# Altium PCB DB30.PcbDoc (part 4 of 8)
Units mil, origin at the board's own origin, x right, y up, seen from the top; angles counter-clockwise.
Board outline 3236.22 x 4456.69 mil, 8 copper layers (Top Layer, MidLayer1, MidLayer2, GND-Layer5, MidLayer3, VCC, MidLayer4, Bottom Layer), stack 61.8 mil thick; 219 components, 472 nets, 1811 pads, 1561 vias.
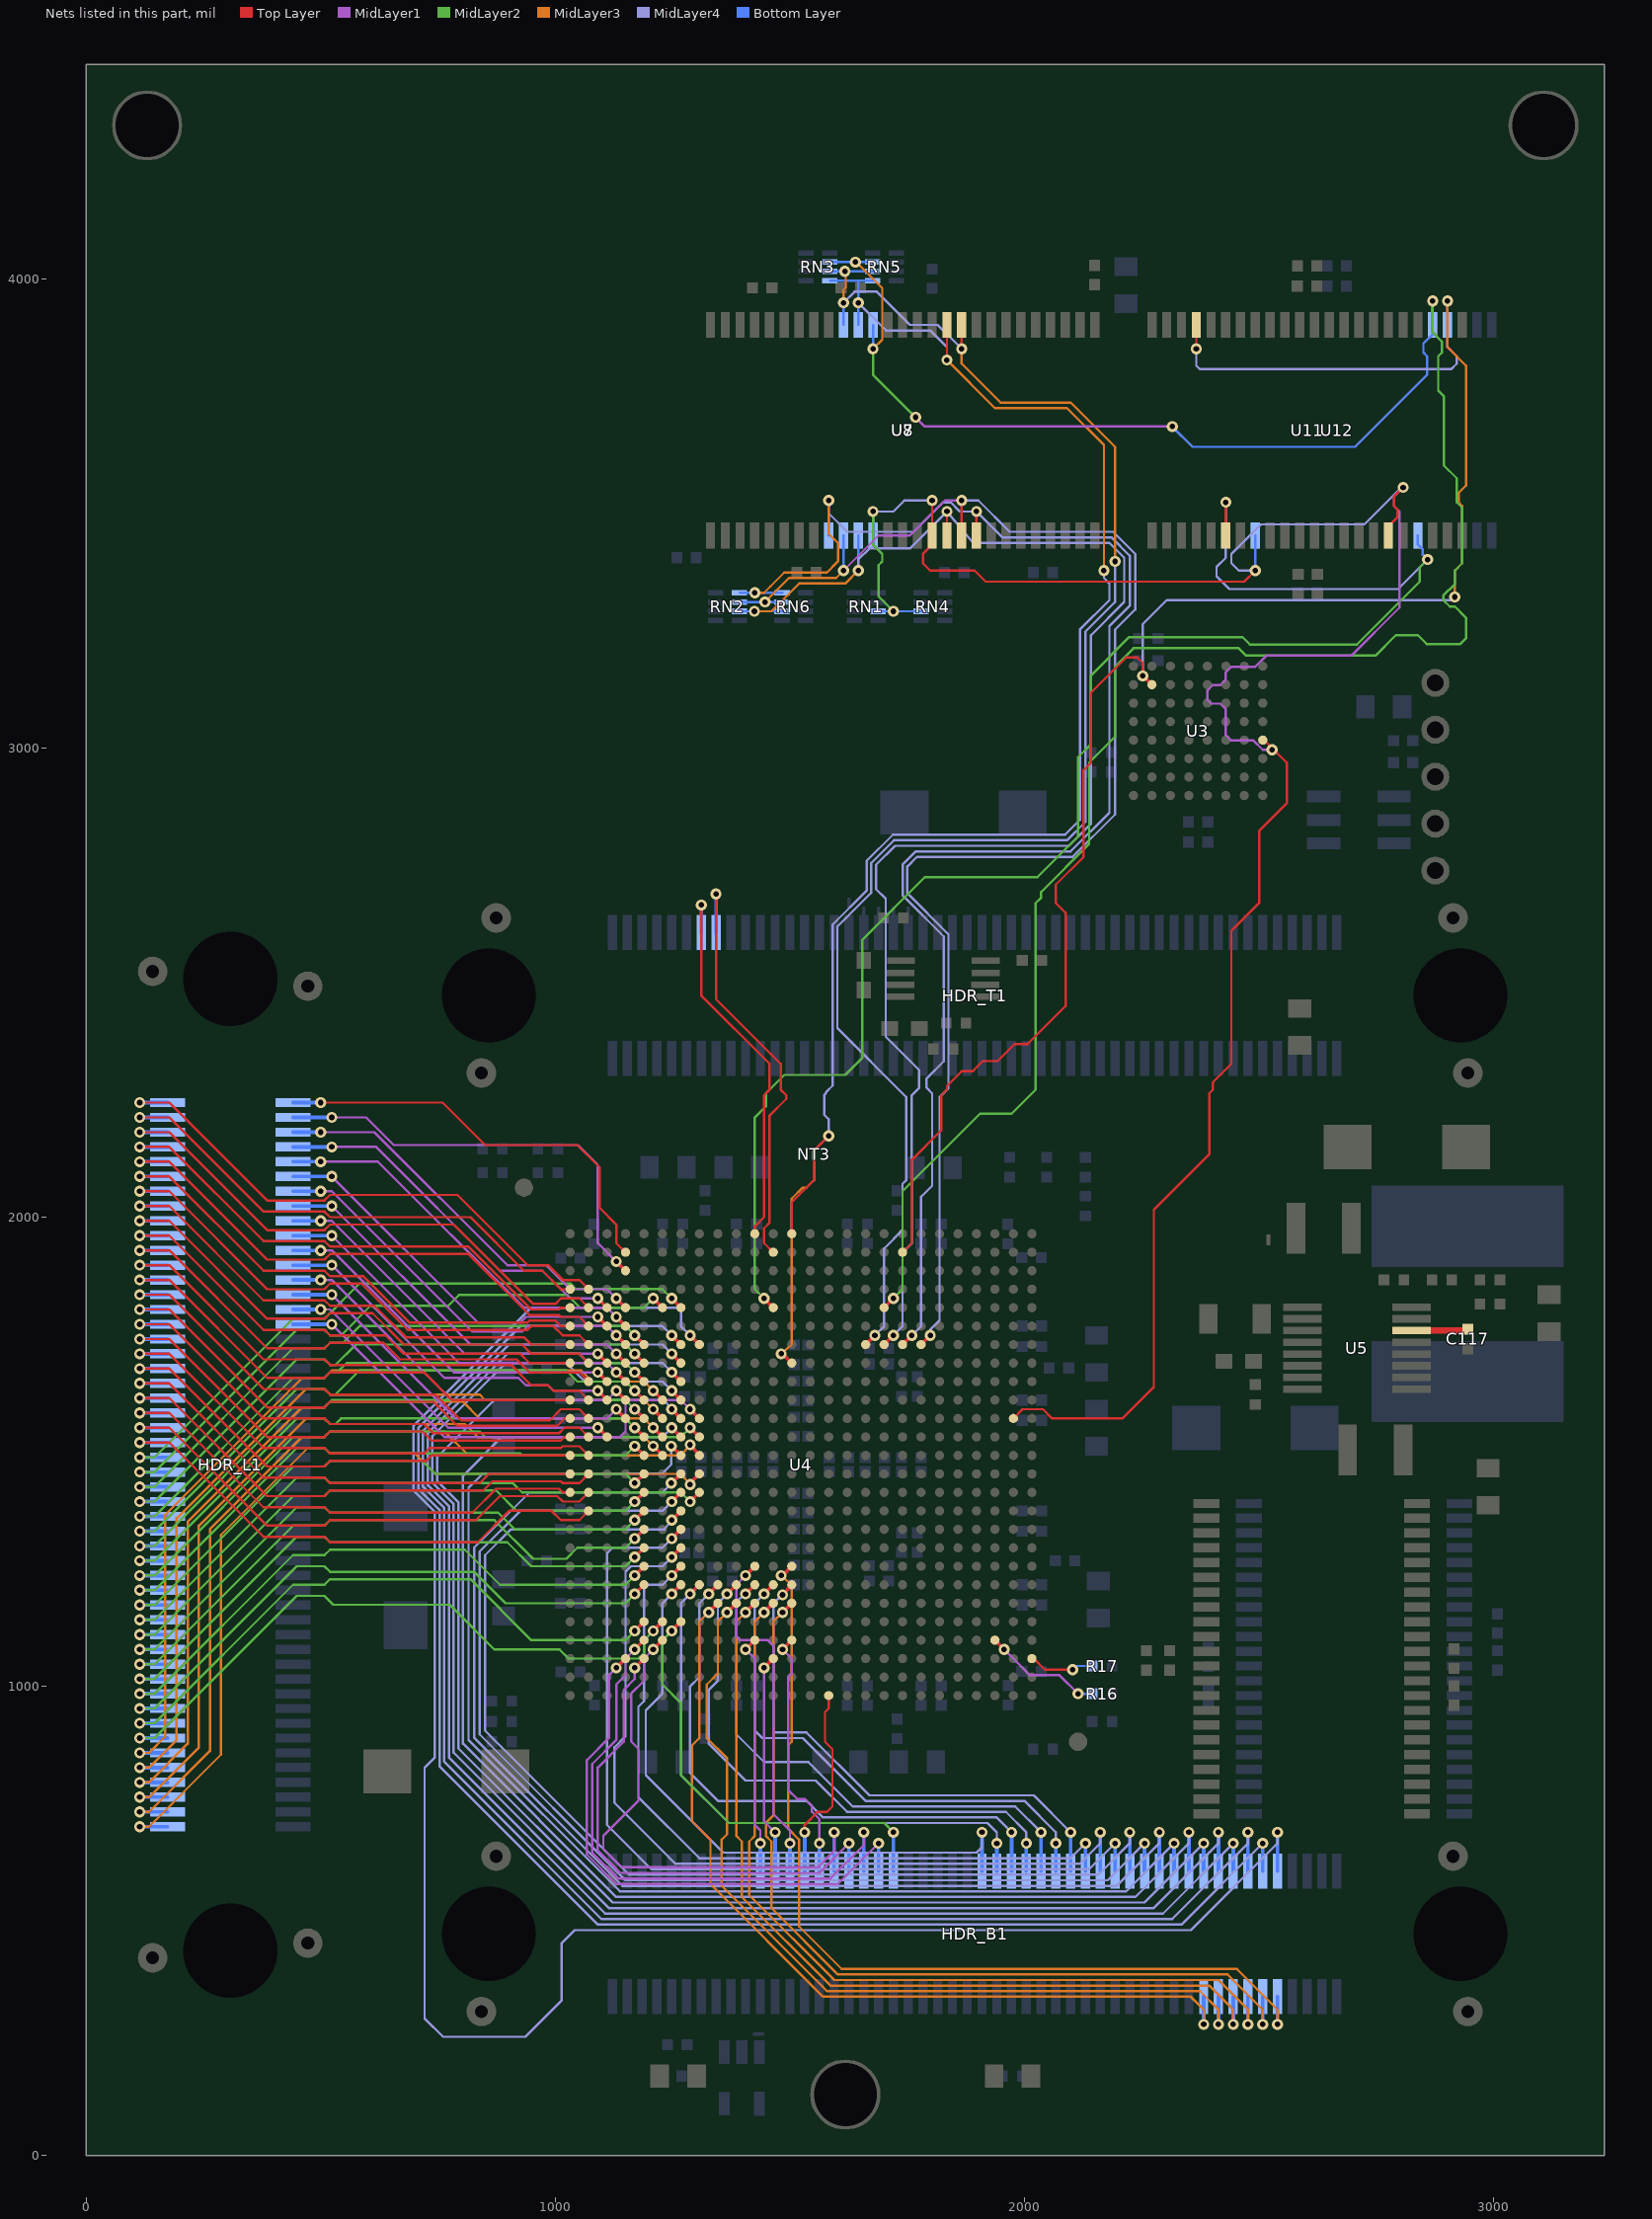
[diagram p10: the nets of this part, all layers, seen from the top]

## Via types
v1: diameter 23.62, hole 11.81, Top Layer to Bottom Layer, 944 vias
v2: diameter 23.62, hole 11.81, Top Layer to Bottom Layer, tented both sides, 477 vias
v3: diameter 27.56, hole 15.75, Top Layer to Bottom Layer, 139 vias
v4: diameter 23.62, hole 11.81, Top Layer to Bottom Layer, tented top, 1 vias

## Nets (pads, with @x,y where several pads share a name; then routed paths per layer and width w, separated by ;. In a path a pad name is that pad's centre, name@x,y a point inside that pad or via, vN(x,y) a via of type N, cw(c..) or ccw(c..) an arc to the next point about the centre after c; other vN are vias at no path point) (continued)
BUS_NBE3: RN3.6 RN5.7 U4.E18 U8.39 U12.40 | length 5096.7
  Top Layer w7.87: U4.E18@1700.79,1807.09 v1(1720.47,1826.77)
  MidLayer1 w5: v2(1767.72,3704.72) 1787.4,3685.04 v2(2314.96,3685.04)
  MidLayer2 w5: v2(1677.17,3850.39) 1677.17,3795.28 v2(1767.72,3704.72) ; v1(1720.47,1826.77) 1740.16,1846.46 1740.16,2027.56 1740.16,2039.37 1740.16,2055.12 1905.51,2220.47 1972.44,2220.47 2023.62,2271.65 2023.62,2669.29 2035.43,2681.1 2035.43,2692.91 2137.8,2795.28 2137.8,2968.5 2192.91,3023.62 2192.91,3173.23 2232.28,3212.6 2456.69,3212.6 2472.44,3196.85 2748.03,3196.85 2791.34,3240.16 2838.58,3240.16 2857.28,3221.46 2929.13,3221.46 2940.94,3233.27 2940.94,3277.56 2917.32,3301.18 2906.5,3301.18 2892.72,3314.96 2892.72,3324.8 2917.32,3349.41 2917.32,3377.95 2933.07,3393.7 2933.07,3511.81 2921.26,3523.62 2921.26,3574.8 2893.7,3602.36 2893.7,3750 2881.89,3761.81 2881.89,3834.65 2889.76,3842.52 2889.76,3866.14 2870.08,3885.83 v2(2870.08,3952.76)
  MidLayer3 w5: v1@1641.54,4035.43 1696.85,3980.12 1696.85,3870.08 v2(1677.17,3850.39)
  Bottom Layer w5: RN3.6@1586.22,4035.43 RN5.7@1677.56,4035.43 ; v2(1677.17,3850.39) U8.39@1677.17,3901.57 ; v2(2314.96,3685.04) 2358.27,3641.73 2704.72,3641.73 2858.27,3795.28 2858.27,3834.65 2850.39,3842.52 2850.39,3862.2 2870.08,3881.89 v2(2870.08,3952.76)
  other v1: 1639.78,4035.43
BUS_NOE: U3.G2 U4.B19 U11.41 U12.41 | length 3948.6
  Top Layer w5: U4.B19@1740.16,1925.2 1759.84,1944.88 1759.84,2027.56 1759.84,2039.37 1759.84,2122.05 1822.83,2185.04 1822.83,2259.84 1834.64,2271.65 1834.64,2279.53 1866.14,2311.02 1889.76,2311.02 1911.17,2332.43 1942.66,2332.43 1978.9,2368.66 2006.46,2368.66 2087.6,2449.8 2087.6,2648.62 2066.93,2669.29 2066.93,2708.66 2125.98,2767.72 2125.98,2952.76 2141.73,2968.5 2141.73,3118.11 2216.54,3192.91 2240.16,3192.91 2251.97,3181.1 v1@2251.97,3154.53 ; v1@2255.91,3150.59 v1@2255.91,3154.53 ; v2(2366.14,3850.39) U11.41@2366.14,3901.57
  Top Layer w7.87: v1@2251.97,3154.53 U3.G2@2271.65,3134.84
  MidLayer3 w5: v2(2901.58,3952.76) 2901.57,3854.33 2940.94,3814.96 2940.94,3559.06 2925.2,3543.31 2925.2,3523.62 2933.07,3515.75 2933.07,3393.7 2917.32,3377.95 2917.32,3314.96 v1(2917.32,3321.85)
  MidLayer4 w5: v1(2251.97,3153.54) 2251.97,3263.78 2303.15,3314.96 2907.48,3314.96 v1(2917.32,3321.85) ; v2(2366.14,3850.39) 2366.14,3814.96 2374.02,3807.09 2909.45,3807.09 2921.26,3818.9 2921.26,3834.65 2901.58,3854.33 v2(2901.58,3952.76)
  Bottom Layer w5: U12.41@2901.57,3901.57 v2(2901.58,3952.76)
BUS_NWE: RN1.7 RN4.6 U3.A5 U4.L25 U7.16 U8.16 U11.17 U12.17 | length 4955.5
  Top Layer w5: U7.16@1803.14,3452.75 v2(1803.14,3527.55) ; U7.16@1803.15,3460.62 1803.15,3433.07 1783.46,3413.39 1783.46,3393.7 1799.21,3377.95 1893.7,3377.95 1917.32,3354.33 2468.5,3354.33 v1(2492.13,3377.95) ; U4.L25@1976.38,1570.87 1996.06,1590.55 2039.37,1590.55 2059.06,1570.87 2078.74,1570.87 2094.49,1570.87 2208.66,1570.87 2275.59,1637.8 2275.59,2015.75 2393.7,2133.86 2393.7,2263.78 2401.57,2271.65 2401.57,2287.4 2440.94,2326.77 2440.94,2610.24 2500,2669.29 2500,2822.83 2559.06,2881.89 2559.06,2968.5 2510.82,3016.74 U3.A5@2507.87,3016.73 ; U11.17@2775.59,3452.76 2775.59,3472.44 2795.28,3492.13 2795.28,3507.87 2787.4,3515.75 2787.4,3535.43 v1(2807.09,3555.12)
  MidLayer1 w5: v1(2527.56,2996.06) 2507.87,2996.06 2488.19,3015.75 2440.94,3015.75 2429.13,3027.56 2429.13,3082.68 2417.32,3094.49 2397.64,3094.49 2389.76,3102.36 2389.76,3122.05 2401.57,3133.86 2417.32,3133.86 2429.13,3145.67 2429.13,3161.42 2440.94,3173.23 2492.13,3173.23 2515.75,3196.85 2696.85,3196.85 2799.21,3299.21 2799.21,3503.94 2787.4,3515.75 2787.4,3535.43 v1(2807.09,3555.12)
  MidLayer2 w5: v2(1677.17,3503.94) 1677.17,3433.07 1696.85,3413.39 1696.85,3397.64 1688.98,3389.76 1688.98,3322.83 v1(1720.47,3291.34)
  MidLayer4 w5: v2(1677.17,3503.94) 1720.47,3503.94 1744.09,3527.55 v2(1803.14,3527.55) ; v1(2492.13,3377.95) 2456.69,3377.95 2440.94,3393.7 2440.94,3413.39 2503.94,3476.38 2724.41,3476.38 v1@2805.12,3557.09
  Bottom Layer w5: U8.16@1677.17,3452.76 v2(1677.17,3503.94) ; RN1.7@1688.18,3291.34 RN4.6@1779.53,3291.34 RN4.6@1779.92,3291.34 ; v1(2492.13,3377.95) U12.17@2492.13,3452.76
BUS_SDRAM_CKE: RN3.7 RN5.6 U4.G17 U7.37 U8.37 | length 3474.1
  Top Layer w5: v2(1866.14,3850.39) U7.37@1866.14,3901.57
  Top Layer w7.87: U4.G17@1661.42,1728.35 v1(1681.1,1748.03)
  MidLayer3 w5: v2(1614.17,3948.82) 1614.17,3976.38 1618.9,3981.11 v1@1618.9,4015.75 ; v2(1866.14,3850.39) 1866.14,3818.9 1948.82,3736.22 2098.43,3736.22 2192.91,3641.73 v1(2192.91,3397.64)
  MidLayer4 w5: v2(1614.17,3948.82) 1637.8,3972.44 1685.04,3972.44 1755.91,3901.57 1814.96,3901.57 v2(1866.14,3850.39) ; v1(1681.1,1748.03) 1700.79,1767.72 1700.79,1933.07 1740.16,1972.44 1740.16,2027.56 1740.16,2043.31 1740.16,2070.87 1748.03,2078.74 1748.03,2255.91 1601.2,2402.74 1601.2,2619.25 1673.05,2691.1 1673.5,2691.1 1673.5,2754.96 1721.69,2803.15 2090.55,2803.15 2129.92,2842.52 2129.92,3248.03 2192.91,3311.02 v1(2192.91,3397.64)
  Bottom Layer w5: RN3.7@1586.22,4015.75 RN5.6@1676.19,4015.75 RN5.6@1677.56,4015.75 ; U8.37@1614.17,3901.57 v2(1614.17,3948.82)
  other v1: 1617.14,4015.75
BUS_SDRAM_CLK: NT3.2 RN3.8 RN5.5 U4.H13 U7.38 U8.38 | length 3458.8
  Top Layer w5: NT3.2@1551.18,2141.73 1562.99,2153.54 v1(1582.68,2173.23) ; v2(1834.64,3826.77) U7.38@1834.65,3901.57
  Top Layer w7.87: v1@1484.25,1708.66 U4.H13@1503.94,1688.98
  MidLayer3 w5: v1(1481.3,1708.66) 1503.94,1728.35 1503.94,2027.56 1503.94,2039.37 1527.56,2062.99 1535.43,2062.99 1551.18,2078.74 1551.18,2141.73 v1(1582.68,2173.23) ; v2(1834.64,3826.77) 1937,3724.41 2090.55,3724.41 2169.29,3645.67 v1(2169.29,3377.95)
  MidLayer4 w5: v1(1582.68,2173.23) 1582.68,2208.66 1573,2218.34 1573,2260.09 1576.99,2264.08 1576.99,2266.23 1591.2,2280.43 1591.2,2623.39 1663.5,2695.69 1663.5,2759.1 1719.36,2814.96 2086.61,2814.96 2118.11,2846.46 2118.11,3251.97 2181.1,3314.96 2181.1,3350.39 2169.29,3362.2 v1(2169.29,3377.95) ; v2(1645.67,3948.82) 1704.72,3889.76 1799.21,3889.76 1834.64,3854.34 v2(1834.64,3826.77)
  Bottom Layer w5: RN3.8@1586.22,3996.06 RN5.5@1677.56,3996.06 ; U8.38@1645.67,3901.57 1645.67,3996.06
BUS_SDRAM_FEEDBACK: NT3.1 U4.A13 | length 181
  Top Layer w5: U4.A13@1503.94,1964.57 1503.94,2031.5 1551.18,2078.74 NT3.1@1551.18,2125.98
BUS_SDRAM_NCAS: RN2.7 RN6.6 U4.G18 U7.17 U8.17 | length 3334.5
  Top Layer w5: U7.17@1834.65,3452.76 1834.64,3499.99 v1(1834.65,3503.94)
  Top Layer w7.87: U4.G18@1700.79,1728.35 v1(1720.47,1748.03)
  MidLayer3 w5: v1(1424.23,3291.34) 1460.63,3291.34 1519.68,3350.39 1618.11,3350.39 v2(1645.67,3377.95)
  MidLayer4 w5: v2(1645.67,3377.95) 1645.67,3401.57 1669.29,3425.2 1755.91,3425.2 v1(1834.65,3503.94) 1890.42,3437.01 2181.1,3437.01 2212.6,3405.51 2212.6,3311.02 2141.73,3240.16 2141.73,2838.58 2094.49,2791.34 1724.02,2791.34 1683.5,2750.82 1683.5,2699.24 1704.26,2678.48 1704.26,2384.54 1775.59,2313.21 1775.59,2275.59 1759.84,2259.84 1759.84,2043.31 1759.84,2027.56 1759.84,1944.88 1740.16,1925.2 1740.16,1767.72 v1(1720.47,1748.03)
  Bottom Layer w5: RN2.7@1393.3,3291.34 RN6.6@1483.28,3291.34 RN6.6@1484.64,3291.34 ; v2(1645.67,3377.95) U8.17@1645.67,3452.76
BUS_SDRAM_NCS: RN2.5 RN6.8 U4.G19 U7.19 U8.19 | length 3476.3
  Top Layer w5: U7.19@1897.64,3452.76 v2(1897.63,3503.93)
  Top Layer w7.87: U4.G19@1740.16,1728.35 v1(1759.84,1748.03)
  MidLayer3 w5: v1(1425.2,3330.71) 1444.88,3330.71 1458.54,3344.36 1488.19,3374.02 1578.74,3374.02 1602.36,3397.64 1602.36,3437.01 1582.68,3456.69 v2(1582.68,3527.56)
  MidLayer4 w5: v2(1582.68,3527.56) 1582.68,3500 1622.05,3460.63 1763.78,3460.63 1826.77,3523.62 1842.52,3523.62 1862.21,3503.93 v2(1897.63,3503.93) 1952.76,3448.82 2185.04,3448.82 2224.41,3409.45 2224.41,3303.15 2181.1,3259.84 2181.1,2862.2 2098.43,2779.53 1768.23,2779.53 1740.3,2751.6 1740.3,2685.86 1827.88,2598.27 1827.88,2332.12 1791.34,2295.57 1791.34,2275.59 1803.15,2263.78 1803.15,2066.93 1779.53,2043.31 1779.53,2027.56 1779.53,1767.72 v1(1759.84,1748.03)
  Bottom Layer w5: RN2.5@1393.31,3330.71 RN6.8@1483.28,3330.71 RN6.8@1484.26,3330.71 ; U8.19@1582.68,3452.76 v2(1582.68,3527.56)
BUS_SDRAM_NRAS: RN2.6 RN6.7 U4.G20 U7.18 U8.18 | length 3317.2
  Top Layer w5: U7.18@1866.14,3452.76 v1(1866.14,3527.55)
  Top Layer w7.87: U4.G20@1779.53,1728.35 v1(1799.21,1748.03)
  MidLayer1 w5: v2(1614.17,3377.95) 1688.98,3452.76 1755.91,3452.76 1830.7,3527.55 v1(1866.14,3527.55)
  MidLayer3 w5: v1(1446.86,3311.02) 1498.05,3362.2 1598.43,3362.2 v2(1614.17,3377.95)
  MidLayer4 w5: v1(1799.21,1748.03) 1799.21,1760.01 1818.9,1779.7 1818.9,2027.56 1818.9,2043.31 1818.9,2255.91 1837.88,2274.89 1837.88,2602.42 1750.3,2690 1750.3,2747.46 1770.56,2767.72 2102.36,2767.72 2192.91,2858.27 2192.91,3251.97 2236.22,3295.28 2236.22,3413.39 2188.98,3460.63 1968.5,3460.63 1901.58,3527.55 v1(1866.14,3527.55) v1@1858.27,3531.5
  Bottom Layer w5: RN2.6@1393.3,3311.02 RN6.7@1483.28,3311.03 RN6.7@1484.64,3311.02 ; v2(1614.17,3377.95) U8.18@1614.17,3452.76
BUS_SRAM_NCS: U4.E12 U11.6 U12.6 | length 3511.7
  Top Layer w5: U11.6@2429.13,3452.76 2429.13,3503.94 v2(2429.13,3523.62)
  Top Layer w7.87: v1(1444.88,1826.77) U4.E12@1464.57,1807.09
  MidLayer2 w5: v1(1444.88,1826.77) 1425.2,1846.46 1425.2,2027.56 1425.2,2039.37 1425.2,2212.6 1448.82,2236.22 1448.82,2244.09 1448.82,2263.78 1488.19,2303.15 1618.11,2303.15 1654.53,2339.57 1654.53,2591.54 1787.4,2724.41 2027.56,2724.41 2114.17,2811.02 2114.17,2980.32 2141.73,3007.87 2141.73,3154.53 2223.42,3236.22 2464.57,3236.22 2480.32,3220.47 2708.66,3220.47 2842.52,3354.33 2842.52,3384.83 v2(2859.27,3401.57)
  MidLayer4 w5: v2(2429.13,3523.62) 2429.13,3405.51 2409.45,3385.83 2409.45,3366.14 2437.01,3338.58 2796.28,3338.58 v2(2859.27,3401.57)
  Bottom Layer w5: U12.6@2838.58,3452.76 2838.58,3433.42 2848.92,3423.08 2848.92,3411.92 v2(2859.27,3401.57)
BUZZER: HDR_B1.40 U4.AB7 | length 945.4
  Top Layer w7.87: v1(1248.03,1118.11) U4.AB7@1267.72,1137.8
  MidLayer2 w5: v1(1248.03,1118.11) 1228.35,1098.42 1228.35,1003.94 1267.72,964.57 1267.72,917.32 1267.72,905.51 1267.72,811.02 1370.08,708.66 1700.79,708.66 v2(1720.47,688.98)
  Bottom Layer w7.87: HDR_B1.40@1720.48,606.3 v2(1720.47,688.98)
CAN_RXD: HDR_T1.14 U4.A11 | length 833.2
  Top Layer w5: v2(1311.02,2665.35) 1311.02,2472.44 1456.69,2326.77 1456.69,2271.65 1444.88,2259.84 1444.88,2062.99 1444.88,2039.37 1444.88,2027.56 1444.88,2000 1425.2,1980.31 U4.A11@1425.2,1964.57
  Bottom Layer w7.87: HDR_T1.14@1311.02,2606.3 v2(1311.02,2665.35)
CAN_TXD: HDR_T1.16 U4.B12 | length 936.1
  Top Layer w5: v2(1342.52,2688.98) 1342.52,2464.57 1480.31,2326.77 1480.31,2271.65 1492.13,2259.84 1492.13,2251.97 1456.69,2216.54 1456.69,2039.37 1456.69,2027.56 1456.69,1988.19 1444.88,1976.38 1444.88,1944.88 U4.B12@1464.57,1925.2
  Bottom Layer w7.87: HDR_T1.16@1342.52,2606.3 v2(1342.52,2688.98)
CCLK: R17.2 U4.AD26 | length 152.6
  Top Layer w5: U4.AD26@2015.75,1059.05 2019.69,1059.05 2043.31,1035.43 v1(2102.36,1035.43)
  Bottom Layer w5: v1(2102.36,1035.43) 2110.24,1043.31 R17.2@2144.17,1043.31 R17.2@2136.3,1035.43
COMP: C117.2 U5.6 | length 121.4
  Top Layer w13.78: U5.6@2824.58,1758.25 2942.3,1758.25 C117.2@2944.88,1760.82
DAU_RESET_SW: HDR_B1.38 U4.AD4 | length 1194.6
  Top Layer w7.87: v1(1129.92,1039.37) U4.AD4@1149.61,1059.05
  MidLayer1 w5: v1(1129.92,1039.37) 1114.17,1023.62 1114.17,917.32 1114.17,905.51 1114.17,889.76 1066.93,842.52 1066.93,641.73 1129.92,578.74 1602.36,578.74 v2(1688.98,665.35)
  Bottom Layer w7.87: HDR_B1.38@1688.98,606.3 v2(1688.98,665.35)
DAU_TFT_BLIGHT: HDR_B1.91 U4.W13 | length 1982.9
  Top Layer w7.87: v1@1484.25,1236.22 U4.W13@1503.94,1255.91
  MidLayer3 w5: v1(1481.3,1236.22) 1503.94,1216.54 1503.94,917.32 1503.94,905.51 1503.94,881.89 1496.06,874.02 1496.06,696.85 1519.68,673.23 1519.68,488.19 1610.24,397.64 2452.76,397.64 2539.37,311.02 v2(2539.37,279.53)
  Bottom Layer w7.87: v2(2539.37,279.53) HDR_B1.91@2539.37,338.58
DAU_TFT_BLUE0: HDR_B1.62 U4.Y12 | length 1141.4
  Top Layer w7.87: v1(1444.88,1196.85) U4.Y12@1464.57,1216.54
  MidLayer4 w5: v1(1444.88,1196.85) 1425.19,1177.16 1425.19,917.32 1425.2,905.51 1440.94,889.76 1527.56,889.76 1661.42,755.91 2000,755.91 2066.93,688.98 v2(2066.93,665.35)
  Bottom Layer w7.87: HDR_B1.62@2066.93,606.3 v2(2066.93,665.35)
DAU_TFT_BLUE1: HDR_B1.64 U4.Y13 | length 1133.6
  Top Layer w7.87: v1(1484.25,1194.88) U4.Y13@1503.94,1216.54
  MidLayer4 w5: v1(1484.25,1194.88) 1464.57,1177.16 1464.57,917.32 1464.57,905.51 1468.5,901.57 1535.43,901.57 1669.29,767.72 2019.68,767.72 v2(2098.42,688.98)
  Bottom Layer w7.87: v2(2098.42,688.98) HDR_B1.64@2098.43,606.3
DAU_TFT_BLUE2: HDR_B1.66 U4.W7 | length 1626.8
  Top Layer w7.87: v1(1248.03,1236.22) U4.W7@1267.72,1255.91
  MidLayer4 w5: v1(1248.03,1236.22) 1228.34,1216.53 1196.85,1216.53 1188.98,1208.66 1188.98,968.5 1177.17,956.69 1177.17,917.32 1177.17,905.51 1177.17,763.78 1307.09,633.86 2098.43,633.86 v2(2129.92,665.35)
  Bottom Layer w7.87: HDR_B1.66@2129.92,606.3 v2(2129.92,665.35)
DAU_TFT_BLUE3: HDR_B1.68 U4.V7 | length 1854.7
  Top Layer w7.87: v1(1248.03,1275.59) U4.V7@1267.72,1295.28
  MidLayer4 w5: v1(1248.03,1275.59) 1228.34,1255.9 1161.42,1255.9 1149.61,1244.09 1149.61,917.32 1149.61,905.51 1149.61,893.7 1125.98,870.08 1125.98,751.97 1255.91,622.05 2118.11,622.05 2161.42,665.35 v2(2161.42,688.98)
  Bottom Layer w7.87: HDR_B1.68@2161.42,606.3 v2(2161.42,688.98)
DAU_TFT_BLUE4: HDR_B1.70 U4.U7 | length 1961.1
  Top Layer w7.87: v1(1248.03,1314.96) U4.U7@1267.72,1334.65
  MidLayer4 w5: v1(1248.03,1314.96) 1228.35,1295.28 1122.05,1295.28 1110.24,1283.46 1110.24,917.32 1110.24,905.51 1110.24,704.72 1204.72,610.24 2137.8,610.24 v2(2192.91,665.35)
  Bottom Layer w7.87: HDR_B1.70@2192.92,606.3 v2(2192.91,665.35)
DAU_TFT_CL1: HDR_B1.88 U4.H7 | length 3391.7
  Top Layer w7.87: v1(1248.03,1708.66) U4.H7@1267.72,1688.98
  MidLayer4 w5: v1(1248.03,1708.66) 1228.34,1728.35 968.5,1728.35 956.69,1728.35 901.57,1728.35 717.9,1544.67 717.9,1425.57 763.15,1380.32 763.15,839.21 1098.43,503.94 2314.96,503.94 2476.38,665.35 v2(2476.38,688.98)
  Bottom Layer w7.87: HDR_B1.88@2476.38,606.3 v2(2476.38,688.98)
DAU_TFT_CL2: HDR_B1.90 U4.G7 | length 3490.1
  Top Layer w7.87: v1(1248.03,1748.03) U4.G7@1267.72,1728.35
  MidLayer4 w5: v1(1248.03,1748.03) 1228.34,1767.72 968.51,1767.72 956.69,1767.72 925.2,1767.72 707.9,1550.42 707.9,1421.43 753.15,1376.18 753.15,829.53 1090.55,492.13 2334.65,492.13 v2(2507.87,665.35)
  Bottom Layer w7.87: v2(2507.87,665.35) HDR_B1.90@2507.88,606.3 v2(2507.87,665.35)
DAU_TFT_CL3: HDR_B1.92 U4.G8 | length 4238.6
  Top Layer w7.87: v1(1287.4,1748.03) U4.G8@1307.09,1728.35
  MidLayer4 w5: v1(1287.4,1748.03) 1267.71,1767.72 1267.71,1799.21 1259.84,1807.09 968.5,1807.09 956.69,1807.09 948.82,1807.09 697.9,1556.17 697.9,1417.29 743.15,1372.04 743.15,848.46 721.46,826.77 721.46,292.32 760.83,252.95 936.02,252.95 1013.78,330.71 1013.78,452.76 1041.34,480.32 2354.33,480.32 2539.37,665.35 v2(2539.37,688.98)
  Bottom Layer w7.87: HDR_B1.92@2539.37,606.3 v2(2539.37,688.98)
DAU_TFT_DISP_ON: HDR_B1.89 U4.AA13 | length 1904.8
  Top Layer w7.87: v1(1484.25,1157.48) U4.AA13@1503.94,1177.17
  MidLayer3 w5: v1(1484.25,1157.48) 1464.57,1137.79 1464.57,917.32 1464.57,905.51 1464.57,724.41 1448.82,708.66 1448.82,681.1 1460.63,669.29 1460.63,527.56 1602.36,385.83 2433.07,385.83 2507.87,311.02 v2(2507.88,279.53)
  Bottom Layer w7.87: v2(2507.88,279.53) HDR_B1.89@2507.88,338.58
DAU_TFT_GREEN0: HDR_B1.72 U4.T7 | length 2467
  Top Layer w7.87: v1(1248.03,1354.33) U4.T7@1267.72,1374.02
  MidLayer4 w5: v1(1248.03,1354.33) 1232.28,1334.65 1078.74,1334.64 968.5,1334.64 956.69,1334.65 905.51,1334.65 850.39,1279.53 850.39,905.51 1157.48,598.43 2157.48,598.43 2224.41,665.36 v2(2224.41,688.98)
  Bottom Layer w7.87: HDR_B1.72@2224.41,606.3 v2(2224.41,688.98)
DAU_TFT_GREEN1: HDR_B1.74 U4.R7 | length 2508.9
  Top Layer w7.87: v1(1248.03,1393.7) U4.R7@1267.72,1413.39
  MidLayer4 w5: v1(1248.03,1393.7) 1228.34,1374.01 1059.06,1374.01 968.5,1374.01 956.69,1374.02 925.2,1374.02 838.58,1287.4 838.58,897.64 1149.61,586.61 2177.16,586.61 v2(2255.9,665.35)
  Bottom Layer w7.87: HDR_B1.74@2255.91,606.3 v2(2255.9,665.35)
DAU_TFT_GREEN2: HDR_B1.76 U4.P7 | length 2646
  Top Layer w7.87: v1@1248.03,1433.07 U4.P7@1267.72,1452.76
  MidLayer4 w5: v1@1248.03,1433.07 1247.54,1432.58 1228.34,1413.38 968.5,1413.39 956.69,1413.39 944.88,1413.39 826.77,1295.28 826.77,890.75 1142.72,574.8 2196.85,574.8 2287.4,665.35 v2(2287.4,688.98)
  Bottom Layer w7.87: HDR_B1.76@2287.41,606.3 v2(2287.4,688.98)
  other v1: 1247.05,1433.07
DAU_TFT_GREEN3: HDR_B1.78 U4.N7 | length 2796.4
  Top Layer w7.87: v1@1248.03,1511.81 U4.N7@1267.72,1492.13
  MidLayer4 w5: v1(1247.05,1511.81) 1247.05,1473.05 1227,1453 844.96,1453 814.96,1423 814.96,885.83 1137.8,562.99 2216.53,562.99 v2(2318.9,665.35) ; v1@1247.54,1512.3 v1@1248.03,1511.81
  Bottom Layer w7.87: HDR_B1.78@2318.9,606.3 v2(2318.9,665.35)
DAU_TFT_GREEN4: HDR_B1.80 U4.M7 | length 2922.2
  Top Layer w7.87: v1(1248.03,1551.18) U4.M7@1267.72,1531.5
  MidLayer4 w5: v1(1248.03,1551.18) 1228.34,1531.5 885.83,1531.5 803.15,1448.82 803.15,877.95 1129.92,551.18 2236.22,551.18 2350.39,665.35 v2(2350.39,688.98)
  Bottom Layer w7.87: HDR_B1.80@2350.4,606.3 v2(2350.39,688.98)
DAU_TFT_GREEN5: HDR_B1.82 U4.L7 | length 3062.8
  Top Layer w7.87: v1(1248.03,1590.55) U4.L7@1267.72,1570.87
  MidLayer4 w5: v1(1248.03,1590.55) 1232.28,1610.24 1078.74,1610.24 968.5,1610.24 956.69,1610.24 870.08,1610.24 747.9,1488.06 747.9,1438 793.15,1392.75 793.15,868.27 1122.05,539.37 2255.9,539.37 v2(2381.89,665.35)
  Bottom Layer w7.87: HDR_B1.82@2381.89,606.3 v2(2381.89,665.35)
DAU_TFT_IRQ: HDR_B1.81 U4.AA9 | length 1890.2
  Top Layer w7.87: v1(1326.77,1157.48) U4.AA9@1346.46,1177.17
  MidLayer3 w5: v1(1326.77,1157.48) 1307.08,1137.79 1307.09,917.32 1307.09,905.51 1307.09,889.76 1291.34,874.02 1291.34,712.6 1330.71,673.23 1330.71,578.74 1570.87,338.58 2354.33,338.58 2381.89,311.02 v2(2381.89,279.53)
  Bottom Layer w7.87: v2(2381.89,279.53) HDR_B1.81@2381.89,338.58
DAU_TFT_M: HDR_B1.87 U4.AA12 | length 1897.9
  Top Layer w7.87: v1(1444.88,1157.48) U4.AA12@1464.57,1177.17
  MidLayer3 w5: v1(1444.88,1157.48) 1425.2,1137.79 1425.2,917.32 1425.2,905.51 1425.2,681.1 1413.39,669.29 1413.39,555.12 1594.49,374.02 2413.39,374.02 2476.38,311.02 v2(2476.38,279.53)
  Bottom Layer w7.87: v2(2476.38,279.53) HDR_B1.87@2476.38,338.58
DAU_TFT_MUX: HDR_B1.85 U4.AA11 | length 1884.5
  Top Layer w7.87: v1(1405.51,1157.48) U4.AA11@1425.2,1177.17
  MidLayer3 w5: v1(1405.51,1157.48) 1385.83,1137.79 1385.83,917.32 1385.83,905.51 1385.83,681.1 1397.64,669.29 1397.64,551.18 1586.61,362.2 2393.7,362.2 2444.88,311.02 v2(2444.88,279.53)
  Bottom Layer w7.87: v2(2444.88,279.53) HDR_B1.85@2444.89,338.58
DAU_TFT_POL: HDR_B1.83 U4.AA10 | length 1910.2
  Top Layer w7.87: v1(1366.14,1157.48) U4.AA10@1385.83,1177.17
  MidLayer3 w5: v1(1366.14,1157.48) 1346.46,1137.79 1346.46,1027.56 1322.83,1003.94 1322.83,917.32 1322.83,905.51 1322.83,889.76 1366.14,846.46 1366.14,685.04 1354.33,673.23 1354.33,574.8 1578.74,350.39 2374.02,350.39 2413.39,311.03 v2(2413.39,279.53)
  Bottom Layer w7.87: v2(2413.39,279.53) HDR_B1.83@2413.39,338.58
DAU_TFT_RED0: HDR_B1.52 U4.Y7 | length 1340.6
  Top Layer w7.87: v1(1248.03,1196.85) U4.Y7@1267.72,1216.54
  MidLayer4 w5: v1(1248.03,1196.85) 1228.34,1177.16 1228.34,984.25 1192.91,948.82 1192.91,917.32 1192.91,905.51 1192.91,811.02 1358.27,645.67 1897.64,645.67 1909.45,657.48 v2(1909.45,688.98)
  Bottom Layer w7.87: HDR_B1.52@1909.45,606.3 v2(1909.45,688.98)
DAU_TFT_RED1: HDR_B1.54 U4.Y8 | length 1228.3
  Top Layer w7.87: v1(1287.4,1196.85) U4.Y8@1307.09,1216.54
  MidLayer4 w5: v1(1287.4,1196.85) 1267.71,1177.16 1267.72,917.32 1267.72,905.51 1267.72,811.02 1370.08,708.66 1921.26,708.66 1940.94,688.98 v2(1940.94,665.35)
  Bottom Layer w7.87: HDR_B1.54@1940.95,606.3 v2(1940.94,665.35)
DAU_TFT_RED2: HDR_B1.56 U4.Y9 | length 1245.9
  Top Layer w7.87: v1(1326.77,1196.85) U4.Y9@1346.46,1216.54
  MidLayer4 w5: v1(1326.77,1196.85) 1307.08,1177.16 1307.08,1019.69 1287.4,1000 1287.4,917.32 1287.4,905.51 1287.4,814.96 1346.46,755.91 1535.43,755.91 1570.87,720.47 1940.94,720.47 v2(1972.44,688.98)
  Bottom Layer w7.87: HDR_B1.56@1972.44,606.3 v2(1972.44,688.98)
DAU_TFT_RED3: HDR_B1.58 U4.Y10 | length 1201.2
  Top Layer w7.87: v1(1366.14,1196.85) U4.Y10@1385.83,1216.54
  MidLayer4 w5: v1(1366.14,1196.85) 1346.46,1177.16 1346.46,1011.81 1326.77,992.13 1326.77,917.32 1326.77,905.51 1326.77,877.95 1405.51,799.21 1555.12,799.21 1622.05,732.28 1960.63,732.28 2003.94,688.98 v2(2003.94,665.35)
  Bottom Layer w7.87: HDR_B1.58@2003.94,606.3 v2(2003.94,665.35)
DAU_TFT_RED4: HDR_B1.60 U4.Y11 | length 1155.2
  Top Layer w7.87: v1(1405.51,1196.85) U4.Y11@1425.2,1216.54
  MidLayer4 w5: v1(1405.51,1196.85) 1385.83,1181.1 1385.82,1027.56 1385.82,917.32 1385.83,905.51 1385.83,897.64 1444.88,838.58 1539.37,838.58 1633.86,744.09 1980.31,744.09 v2(2035.43,688.98)
  Bottom Layer w7.87: HDR_B1.60@2035.44,606.3 v2(2035.43,688.98)
DAU_TFT_STH: HDR_B1.86 U4.J7 | length 3274.1
  Top Layer w7.87: v1(1248.03,1669.29) U4.J7@1267.72,1649.61
  MidLayer4 w5: v1(1248.03,1669.29) 1228.34,1688.98 1070.87,1688.98 1051.18,1708.66 968.5,1708.66 956.69,1708.66 897.64,1708.66 727.9,1538.93 727.9,1429.72 773.15,1384.47 773.15,848.9 1106.3,515.75 2295.28,515.75 v2(2444.88,665.35)
  Bottom Layer w7.87: HDR_B1.86@2444.89,606.3 v2(2444.88,665.35)
DAU_TFT_STV: HDR_B1.84 U4.K7 | length 3251
  Top Layer w7.87: v1(1248.03,1629.92) U4.K7@1267.72,1610.24
  MidLayer4 w5: v1(1248.03,1629.92) 1228.35,1649.61 1062.99,1649.61 1023.62,1688.98 968.5,1688.98 956.69,1688.98 893.7,1688.98 771.18,1566.45 737.9,1533.18 737.9,1433.86 783.15,1388.61 783.15,858.58 1114.17,527.56 2275.59,527.56 2413.38,665.35 v2(2413.38,688.98)
  Bottom Layer w7.87: HDR_B1.84@2413.39,606.3 v2(2413.38,688.98)
DIP0: HDR_B1.22 U4.AC11 | length 513.3
  Top Layer w7.87: v1(1405.51,1078.74) U4.AC11@1425.2,1098.43
  MidLayer1 w5: v1(1405.51,1078.74) 1425.19,1059.05 1425.19,917.32 1425.2,905.51 1425.2,704.72 1437.01,692.91 v2(1437.01,665.35)
  Bottom Layer w7.87: HDR_B1.22@1437.01,606.3 v2(1437.01,665.35)
DIP1: HDR_B1.24 U4.AD12 | length 470.7
  Top Layer w7.87: v1(1444.88,1039.37) U4.AD12@1464.57,1059.05
  MidLayer1 w5: v1(1444.88,1039.37) 1444.88,893.7 1444.88,712.6 v2(1468.5,688.98)
  Bottom Layer w7.87: HDR_B1.24@1468.51,606.3 v2(1468.5,688.98)
DIP2: HDR_B1.26 U4.W11 | length 747.8
  Top Layer w7.87: v1(1405.51,1236.22) U4.W11@1425.2,1255.91
  MidLayer1 w5: v1(1405.51,1236.22) 1385.83,1216.53 1385.83,1106.3 1393.7,1098.43 1452.76,1098.43 1464.57,1086.61 1464.57,917.32 1464.57,905.51 1464.57,728.35 1500,692.91 v2(1500,665.35)
  Bottom Layer w7.87: HDR_B1.26@1500,606.3 v2(1500,665.35)
DIP3: HDR_B1.28 U4.AF15 | length 419.8
  Top Layer w5: v2(1531.5,688.98) 1531.5,704.72 1559.06,732.28 1578.74,732.28 1590.55,744.09 1590.55,866.14 1574.8,881.89 1574.8,905.51 1574.8,917.32 1574.8,944.88 1582.68,952.76 U4.AF15@1582.68,980.31
  Bottom Layer w7.87: HDR_B1.28@1531.5,606.3 v2(1531.5,688.98)
DIP4: HDR_B1.30 U4.AC13 | length 548.8
  Top Layer w7.87: v1(1484.25,1078.74) U4.AC13@1503.94,1098.43
  MidLayer1 w5: v1(1484.25,1078.74) 1503.94,1059.05 1503.94,1027.56 1496.06,1019.69 1496.06,917.32 1496.06,905.51 1496.06,779.53 1515.75,759.84 1532.13,759.84 1547.56,744.41 ; 1547.24,744.09 1547.24,732.28 1562.99,716.54 v2(1562.99,665.35)
  Bottom Layer w7.87: HDR_B1.30@1562.99,606.3 v2(1562.99,665.35)
DIP5: HDR_B1.32 U4.AC6 | length 1155.3
  Top Layer w7.87: v1(1208.66,1078.74) U4.AC6@1228.35,1098.43
  MidLayer1 w5: v1(1208.66,1078.74) 1188.98,1059.05 1188.98,1011.81 1161.42,984.25 1161.42,917.32 1161.42,905.51 1161.42,882.87 1177.17,867.13 1177.17,755.91 1102.36,681.1 1102.36,653.54 1141.73,614.17 1559.06,614.17 1594.49,649.61 v2(1594.49,688.98)
  Bottom Layer w7.87: HDR_B1.32@1594.49,606.3 v2(1594.49,688.98)
DIP6: HDR_B1.34 U4.AD5 | length 1090.4
  Top Layer w7.87: v1(1169.29,1039.37) U4.AD5@1188.98,1059.05
  MidLayer1 w5: v1(1169.29,1039.37) 1169.29,1015.75 1145.67,992.13 1145.67,917.32 1145.67,905.51 1145.67,881.89 1090.55,826.77 1090.55,649.61 1137.8,602.36 1562.99,602.36 v2(1625.98,665.35)
  Bottom Layer w7.87: HDR_B1.34@1625.99,606.3 v2(1625.98,665.35)
DIP7: HDR_B1.36 U4.AC5 | length 1239.6
  Top Layer w7.87: v1(1169.29,1078.74) U4.AC5@1188.98,1098.43
  MidLayer1 w5: v1(1169.29,1078.74) 1149.61,1059.05 1149.61,1023.62 1129.92,1003.94 1129.92,917.32 1129.92,905.51 1129.92,885.83 1078.74,834.65 1078.74,645.67 1133.86,590.55 1586.61,590.55 1657.48,661.42 v2(1657.48,688.98)
  Bottom Layer w7.87: HDR_B1.36@1657.48,606.3 v2(1657.48,688.98)
DONE: R16.2 U4.AC24 | length 256
  Top Layer w7.87: U4.AC24@1937.01,1098.43 v1(1956.69,1078.74)
  MidLayer1 w5: v1(1956.69,1078.74) 1996.71,1038.72 2011.81,1023.62 2074.8,1023.62 v1(2114.17,984.25)
  Bottom Layer w5: v1(2114.17,984.25) R16.2@2144.17,984.25 R16.2@2145.67,984.25
EXTEND_A0: HDR_L1.1 U4.D2 | length 1190.2
  Top Layer w5: v2(114.17,2244.09) 177.17,2244.09 385.83,2035.43 507.88,2035.43 519.69,2047.24 791.34,2047.24 940.94,1897.64 956.69,1897.64 968.5,1897.64 984.25,1897.64 1015.75,1866.14 1051.18,1866.14 U4.D2@1070.87,1846.46
  Bottom Layer w7.87: v2(114.17,2244.09) HDR_L1.1@173.23,2244.09
EXTEND_A1: HDR_L1.3 U4.D1 | length 1143.8
  Top Layer w5: v2(114.17,2212.6) 153.54,2212.6 ; 137.8,2212.6 177.17,2212.6 377.95,2011.81 507.88,2011.81 519.69,2000 818.9,2000 933.07,1885.83 956.69,1885.83 968.5,1885.83 972.44,1885.83 1011.81,1846.46 U4.D1@1031.5,1846.46
  Bottom Layer w7.87: v2(114.17,2212.6) HDR_L1.3@173.23,2212.6
EXTEND_A2: HDR_L1.5 U4.E2 | length 1209.9
  Top Layer w5: v2(114.17,2181.1) 157.48,2181.1 ; 137.8,2181.1 177.17,2181.1 385.83,1972.44 507.88,1972.44 519.69,1984.25 783.46,1984.25 952.76,1814.96 956.69,1814.96 968.5,1814.96 1000,1814.96 1011.81,1826.77 1051.18,1826.77 U4.E2@1070.87,1807.09
  Bottom Layer w7.87: v2(114.17,2181.1) HDR_L1.5@173.23,2181.1
EXTEND_A3: HDR_L1.7 U4.E1 | length 1137.3
  Top Layer w5: v2(114.17,2149.61) 153.54,2149.61 ; 137.8,2149.61 177.17,2149.61 377.95,1948.82 507.88,1948.82 519.69,1937.01 814.96,1937.01 948.82,1803.15 956.69,1803.15 968.5,1803.15 1007.87,1803.15 1011.81,1807.09 U4.E1@1031.5,1807.09
  Bottom Layer w7.87: v2(114.17,2149.61) HDR_L1.7@173.23,2149.6
EXTEND_A4: HDR_L1.9 U4.F2 | length 1182.5
  Top Layer w5: v2(114.17,2118.11) 149.6,2118.11 ; 137.8,2118.11 177.17,2118.11 385.83,1909.45 507.88,1909.45 519.69,1921.26 814.96,1921.26 944.88,1791.34 956.69,1791.34 968.5,1791.34 1007.87,1791.34 1011.81,1787.4 1015.75,1787.4 1047.24,1787.4 1051.18,1787.4 U4.F2@1070.87,1767.72
  Bottom Layer w7.87: v2(114.17,2118.11) HDR_L1.9@173.23,2118.11
EXTEND_A5: HDR_L1.11 U4.F1 | length 1123.5
  Top Layer w5: v2(114.17,2086.62) 149.61,2086.62 ; 137.8,2086.61 177.17,2086.61 377.95,1885.83 507.88,1885.83 519.69,1874.02 590.55,1874.02 688.98,1775.59 940.94,1775.59 944.88,1779.53 956.69,1779.53 968.5,1779.53 1000,1779.53 1011.81,1767.72 U4.F1@1031.5,1767.72
  Bottom Layer w7.87: v2(114.17,2086.62) HDR_L1.11@173.23,2086.61
EXTEND_A6: HDR_L1.13 U4.G2 | length 1179.2
  Top Layer w5: v2(114.17,2055.12) 149.61,2055.12 ; 137.8,2055.12 177.16,2055.12 385.82,1846.46 507.88,1846.46 519.69,1858.27 586.61,1858.27 685.04,1759.84 940.94,1759.84 948.82,1767.72 956.69,1767.72 968.5,1767.72 996.06,1767.72 1015.75,1748.03 1051.18,1748.03 U4.G2@1070.87,1728.35
  Bottom Layer w7.87: v2(114.17,2055.12) HDR_L1.13@173.23,2055.12
EXTEND_A7: HDR_L1.15 U4.G1 | length 1110.5
  Top Layer w5: v2(114.17,2023.62) 149.61,2023.62 ; 137.8,2023.62 177.16,2023.62 377.95,1822.84 507.88,1822.84 519.69,1811.02 614.17,1811.02 681.1,1744.09 933.07,1744.09 948.82,1728.35 956.69,1728.35 968.5,1728.35 U4.G1@1031.5,1728.35
  Bottom Layer w7.87: v2(114.17,2023.62) HDR_L1.15@173.23,2023.62
EXTEND_A8: HDR_L1.17 U4.H2 | length 1162.9
  Top Layer w5: v2(114.17,1992.13) 149.61,1992.13 ; 137.8,1992.13 177.16,1992.13 385.82,1783.47 507.88,1783.47 519.69,1795.28 610.24,1795.28 677.17,1728.35 929.13,1728.35 948.82,1708.66 956.69,1708.66 968.5,1708.66 1051.18,1708.66 U4.H2@1070.87,1688.98
  Bottom Layer w7.87: v2(114.17,1992.13) HDR_L1.17@173.23,1992.12
EXTEND_A9: HDR_L1.19 U4.H1 | length 1100.7
  Top Layer w5: v2(114.17,1960.63) 149.61,1960.63 ; 137.8,1960.63 177.16,1960.63 377.95,1759.84 507.88,1759.84 519.69,1748.03 637.79,1748.03 677.17,1708.66 925.2,1708.66 944.88,1688.98 956.69,1688.98 968.5,1688.98 U4.H1@1031.5,1688.98
  Bottom Layer w7.87: v2(114.17,1960.63) HDR_L1.19@173.23,1960.63
EXTEND_A10: HDR_L1.21 U4.J2 | length 1153.1
  Top Layer w5: v2(114.17,1929.13) 149.61,1929.13 ; 137.8,1929.13 177.16,1929.13 385.82,1720.47 507.88,1720.47 519.69,1732.28 633.86,1732.28 669.29,1696.85 917.32,1696.85 944.88,1669.29 956.69,1669.29 968.5,1669.29 1051.18,1669.29 U4.J2@1070.87,1649.61
  Bottom Layer w7.87: v2(114.17,1929.13) HDR_L1.21@173.23,1929.13
EXTEND_A11: HDR_L1.23 U4.K2 | length 1146.6
  Top Layer w5: v2(114.17,1897.64) 149.61,1897.64 ; 137.8,1897.64 177.16,1897.64 377.95,1696.85 507.88,1696.85 519.69,1685.04 905.51,1685.04 948.82,1641.73 956.69,1641.73 968.5,1641.73 984.25,1641.73 996.06,1629.92 1051.18,1629.92 U4.K2@1070.87,1610.24
  Bottom Layer w7.87: v2(114.17,1897.64) HDR_L1.23@173.23,1897.64
EXTEND_A12: HDR_L1.25 U4.K1 | length 1104
  Top Layer w5: v2(114.17,1866.14) 149.61,1866.14 ; 137.8,1866.14 177.16,1866.14 385.82,1657.48 507.88,1657.48 519.69,1669.29 720.47,1669.29 779.53,1610.24 956.69,1610.24 968.5,1610.24 U4.K1@1031.5,1610.24
  Bottom Layer w7.87: v2(114.17,1866.14) HDR_L1.25@173.23,1866.14
EXTEND_A13: HDR_L1.27 U4.L2 | length 1156.4
  Top Layer w5: v2(114.17,1834.65) 149.61,1834.65 ; 137.8,1834.65 177.16,1834.65 377.95,1633.86 507.87,1633.86 519.69,1622.05 744.09,1622.05 799.21,1566.93 956.69,1566.93 968.5,1566.93 988.19,1566.93 1011.81,1590.55 1051.18,1590.55 U4.L2@1070.87,1570.87
  Bottom Layer w7.87: v2(114.17,1834.65) HDR_L1.27@173.23,1834.64
EXTEND_A14: HDR_L1.29 U4.L1 | length 1103.3
  Top Layer w5: v2(114.17,1803.15) 145.67,1803.15 ; 137.8,1803.15 177.16,1803.15 385.83,1594.49 507.88,1594.49 519.69,1606.3 740.16,1606.3 791.34,1555.12 956.69,1555.12 968.5,1555.12 1003.94,1555.12 1019.69,1570.87 U4.L1@1031.5,1570.87
  Bottom Layer w7.87: v2(114.17,1803.15) HDR_L1.29@173.23,1803.15
EXTEND_A15: HDR_L1.31 U4.M2 | length 1132.9
  Top Layer w5: v2(114.17,1771.65) 145.67,1771.65 ; 137.8,1771.65 177.16,1771.65 377.95,1570.87 507.87,1570.87 519.69,1559.05 720.47,1559.05 740.16,1539.37 956.69,1539.37 968.5,1539.37 1007.87,1539.37 1019.69,1551.18 1051.18,1551.18 U4.M2@1070.87,1531.5
  Bottom Layer w7.87: v2(114.17,1771.65) HDR_L1.31@173.23,1771.65
EXTEND_A16: HDR_L1.33 U4.M1 | length 1087
  Top Layer w5: v2(114.17,1740.16) 145.67,1740.16 ; 137.8,1740.16 177.16,1740.16 385.83,1531.5 507.88,1531.5 519.69,1543.31 716.54,1543.31 736.22,1523.62 956.69,1523.62 968.5,1523.62 996.06,1523.62 1011.81,1523.62 1019.68,1531.5 U4.M1@1031.5,1531.5
  Bottom Layer w7.87: v2(114.17,1740.16) HDR_L1.33@173.23,1740.15
EXTEND_A17: HDR_L1.35 U4.N2 | length 1130.3
  Top Layer w5: v2(114.17,1708.66) 149.61,1708.66 ; 137.8,1708.66 177.16,1708.66 377.95,1507.87 507.87,1507.87 519.69,1496.06 720.47,1496.06 732.28,1507.87 956.69,1507.87 968.5,1507.87 1011.81,1507.87 1015.75,1511.81 1051.18,1511.81 U4.N2@1070.87,1492.13
  Bottom Layer w7.87: v2(114.17,1708.66) HDR_L1.35@173.23,1708.66
EXTEND_A18: HDR_L1.37 U4.N1 | length 1084.4
  Top Layer w5: v2(114.17,1677.17) 149.61,1677.17 ; 137.8,1677.17 177.16,1677.17 385.82,1468.5 507.88,1468.5 519.69,1480.31 724.41,1480.31 736.22,1492.13 956.69,1492.13 968.5,1492.13 U4.N1@1031.5,1492.13
  Bottom Layer w7.87: v2(114.17,1677.17) HDR_L1.37@173.23,1677.16
EXTEND_A19: HDR_L1.39 U4.P1 | length 1084.4
  Top Layer w5: v2(114.17,1645.67) 149.61,1645.67 ; 137.8,1645.67 177.16,1645.67 377.95,1444.88 507.87,1444.88 519.69,1433.07 838.58,1433.07 858.27,1452.76 956.69,1452.76 968.5,1452.76 U4.P1@1031.5,1452.76
  Bottom Layer w7.87: v2(114.17,1645.67) HDR_L1.39@173.23,1645.67
EXTEND_A20: HDR_L1.41 U4.P2 | length 1136.8
  Top Layer w5: v2(114.17,1614.17) 149.61,1614.17 ; 137.8,1614.17 177.16,1614.17 385.82,1405.51 507.88,1405.51 519.69,1417.32 846.45,1417.32 866.14,1437.01 956.69,1437.01 968.5,1437.01 1011.81,1437.01 1015.75,1433.07 1051.18,1433.07 U4.P2@1070.87,1452.76
  Bottom Layer w7.87: v2(114.17,1614.17) HDR_L1.41@173.23,1614.17
EXTEND_A21: HDR_L1.43 U4.R1 | length 1100.7
  Top Layer w5: v2(114.17,1582.68) 149.61,1582.68 ; 137.8,1582.68 177.16,1582.68 377.95,1381.89 507.87,1381.89 519.69,1370.08 822.83,1370.08 874.02,1421.26 956.69,1421.26 968.5,1421.26 1007.87,1421.26 1015.75,1413.39 U4.R1@1031.5,1413.39
  Bottom Layer w7.87: v2(114.17,1582.68) HDR_L1.43@173.23,1582.67
EXTEND_A22: HDR_L1.45 U4.R2 | length 1141.3
  Top Layer w5: v2(114.17,1551.18) 177.16,1551.18 385.82,1342.52 507.88,1342.52 519.69,1354.33 830.71,1354.33 881.89,1405.51 956.69,1405.51 968.5,1405.51 1003.94,1405.51 1015.75,1393.7 1051.18,1393.7 U4.R2@1070.87,1413.39
  Bottom Layer w7.87: v2(114.17,1551.18) HDR_L1.45@173.23,1551.18
EXTEND_A23: HDR_L1.47 U4.T2 | length 1159.7
  Top Layer w5: v2(114.17,1519.69) 149.61,1519.69 ; 137.8,1519.69 177.16,1519.69 377.95,1318.9 507.87,1318.9 519.69,1307.09 834.65,1307.09 901.57,1374.02 956.69,1374.02 968.5,1374.02 992.13,1374.02 1011.81,1354.33 1051.18,1354.33 U4.T2@1070.87,1374.02
  Bottom Layer w7.87: v2(114.17,1519.69) HDR_L1.47@173.23,1519.68
EXTEND_A24: HDR_L1.49 U4.E7 | length 1387.1
  Top Layer w7.87: v1(1248.03,1826.77) U4.E7@1267.72,1807.09
  MidLayer2 w5: v2(114.17,1488.19) 145.67,1488.19 440.94,1783.46 507.87,1783.46 582.68,1858.27 799.21,1858.27 1032.73,1858.27 1044,1847 1044.4,1846.6 1228.2,1846.6 v1(1248.03,1826.77)
  Bottom Layer w7.87: v2(114.17,1488.19) HDR_L1.49@173.23,1488.19
EXTEND_A25: HDR_L1.51 U4.E6 | length 1366.8
  Top Layer w7.87: v1(1208.66,1826.77) U4.E6@1228.35,1807.09
  MidLayer2 w5: v2(114.17,1456.69) 145.67,1456.69 448.82,1759.84 507.87,1759.84 519.68,1748.03 543.31,1748.03 606.3,1811.02 771.65,1811.02 794.63,1834 1026,1834 1053,1807 1188.89,1807 v1(1208.66,1826.77)
  Bottom Layer w7.87: v2(114.17,1456.69) HDR_L1.51@173.23,1456.69
EXTEND_A26: HDR_L1.53 U4.G5 | length 1292
  Top Layer w7.87: v1(1169.29,1748.03) U4.G5@1188.98,1728.35
  MidLayer2 w5: v2(114.17,1425.2) 145.67,1425.2 440.94,1720.47 507.87,1720.47 519.69,1732.28 547.24,1732.28 582.68,1767.72 952.76,1767.72 968.5,1767.72 1149.61,1767.72 v1(1169.29,1748.03)
  Bottom Layer w7.87: v2(114.17,1425.2) HDR_L1.53@173.23,1425.19
EXTEND_A27: HDR_L1.55 U4.H5 | length 1298.6
  Top Layer w7.87: v1(1169.29,1708.66) U4.H5@1188.98,1688.98
  MidLayer2 w5: v2(114.17,1393.7) 145.67,1393.7 448.81,1696.85 507.87,1696.85 519.68,1685.04 531.5,1685.04 574.8,1728.35 952.76,1728.35 968.5,1728.35 1149.61,1728.35 v1(1169.29,1708.66)
  Bottom Layer w7.87: v2(114.17,1393.7) HDR_L1.55@173.23,1393.7
EXTEND_A28: HDR_L1.57 U4.J5 | length 1285.5
  Top Layer w7.87: v1(1169.29,1669.29) U4.J5@1188.98,1649.61
  MidLayer2 w5: v2(114.17,1362.21) 145.67,1362.21 440.94,1657.48 507.87,1657.48 519.69,1669.29 535.43,1669.29 555.12,1688.98 952.76,1688.98 968.5,1688.98 1149.61,1688.98 v1(1169.29,1669.29)
  Bottom Layer w7.87: v2(114.17,1362.21) HDR_L1.57@173.23,1362.2
EXTEND_A29: HDR_L1.59 U4.K5 | length 1311.6
  Top Layer w7.87: v1(1169.29,1629.92) U4.K5@1188.98,1610.24
  MidLayer2 w5: v2(114.17,1330.71) 145.67,1330.71 448.81,1633.86 507.87,1633.86 519.68,1622.05 531.5,1622.05 582.68,1673.23 952.76,1673.23 968.5,1673.23 1023.62,1673.23 1047.24,1649.61 1149.61,1649.61 v1(1169.29,1629.92)
  Bottom Layer w7.87: v2(114.17,1330.71) HDR_L1.59@173.23,1330.71
EXTEND_A30: HDR_L1.61 U4.L5 | length 1279
  Top Layer w7.87: v1(1169.29,1590.55) U4.L5@1188.98,1570.87
  MidLayer2 w5: v2(114.17,1299.21) 145.67,1299.21 440.94,1594.49 507.87,1594.49 523.62,1610.24 952.76,1610.24 968.5,1610.24 1149.61,1610.24 v1(1169.29,1590.55)
  Bottom Layer w7.87: v2(114.17,1299.21) HDR_L1.61@173.23,1299.21
EXTEND_A31: HDR_L1.63 U4.M5 | length 1285.5
  Top Layer w7.87: v1(1169.29,1551.18) U4.M5@1188.98,1531.5
  MidLayer2 w5: v2(114.17,1267.72) 145.67,1267.72 448.81,1570.86 507.87,1570.86 519.68,1559.05 531.49,1559.05 543.31,1570.87 952.76,1570.87 968.5,1570.87 1149.61,1570.87 v1(1169.29,1551.18)
  Bottom Layer w7.87: v2(114.17,1267.72) HDR_L1.63@173.23,1267.71
EXTEND_A32: HDR_L1.65 U4.M8 | length 1400.4
  Top Layer w7.87: v1(1287.4,1551.18) U4.M8@1307.09,1531.5
  MidLayer2 w5: v2(114.17,1236.22) 145.67,1236.22 440.94,1531.49 507.87,1531.49 519.69,1543.31 838.58,1543.31 850.39,1531.5 952.76,1531.5 968.5,1531.5 1267.72,1531.5 v1(1287.4,1551.18)
  Bottom Layer w7.87: v2(114.17,1236.22) HDR_L1.65@173.23,1236.22
EXTEND_A33: HDR_L1.67 U4.N5 | length 1282.3
  Top Layer w7.87: v1(1169.29,1511.81) U4.N5@1188.98,1492.13
  MidLayer2 w5: v2(114.17,1204.72) 145.67,1204.72 448.81,1507.87 507.87,1507.87 519.68,1496.06 925.2,1496.06 929.13,1492.13 952.76,1492.13 968.5,1492.13 1149.6,1492.13 v1(1169.29,1511.81)
  Bottom Layer w7.87: v2(114.17,1204.72) HDR_L1.67@173.23,1204.72
EXTEND_A34: HDR_L1.69 U4.P5 | length 1288.8
  Top Layer w7.87: v1(1169.29,1433.07) U4.P5@1188.98,1452.76
  MidLayer2 w5: v2(114.17,1173.23) 145.67,1173.23 440.94,1468.5 507.87,1468.5 519.69,1480.31 716.54,1480.31 744.09,1452.76 952.76,1452.76 968.5,1452.76 1149.6,1452.76 v1(1169.29,1433.07)
  Bottom Layer w7.87: v2(114.17,1173.23) HDR_L1.69@173.23,1173.23
EXTEND_A35: HDR_L1.71 U4.R8 | length 1406.9
  Top Layer w7.87: v1(1287.4,1393.7) U4.R8@1307.09,1413.39
  MidLayer2 w5: v2(114.17,1141.73) 145.67,1141.73 448.81,1444.88 507.87,1444.88 519.68,1433.07 909.45,1433.07 929.13,1413.39 952.76,1413.39 968.5,1413.39 1267.72,1413.38 v1(1287.4,1393.7)
  Bottom Layer w7.87: v2(114.17,1141.73) HDR_L1.71@173.23,1141.73
EXTEND_A36: HDR_L1.73 U4.R5 | length 1295.3
  Top Layer w7.87: v1(1169.29,1393.7) U4.R5@1188.98,1413.39
  MidLayer2 w5: v2(114.17,1110.24) 145.67,1110.24 440.94,1405.51 507.87,1405.51 519.69,1417.32 874.02,1417.32 917.32,1374.02 956.69,1374.02 968.5,1374.02 1149.61,1374.02 v1(1169.29,1393.7)
  Bottom Layer w7.87: v2(114.17,1110.24) HDR_L1.73@173.23,1110.23
EXTEND_A37: HDR_L1.75 U4.T5 | length 1295.3
  Top Layer w7.87: v1(1169.29,1354.33) U4.T5@1188.98,1374.02
  MidLayer2 w5: v2(114.17,1078.74) 145.67,1078.74 448.81,1381.89 507.87,1381.89 519.68,1370.08 877.95,1370.08 913.39,1334.65 956.69,1334.65 968.5,1334.65 1149.61,1334.65 v1(1169.29,1354.33)
  Bottom Layer w7.87: v2(114.17,1078.74) HDR_L1.75@173.23,1078.74
EXTEND_A38: HDR_L1.77 U4.U5 | length 1321.4
  Top Layer w7.87: v1(1169.29,1314.96) U4.U5@1188.98,1334.65
  MidLayer2 w5: v2(114.17,1047.24) 145.67,1047.24 440.94,1342.52 507.87,1342.52 519.69,1354.33 870.08,1354.33 952.76,1271.65 956.69,1271.65 968.5,1271.65 1023.62,1271.65 1047.24,1295.28 1149.61,1295.28 v1(1169.29,1314.96)
  Bottom Layer w7.87: v2(114.17,1047.24) HDR_L1.77@173.23,1047.24
EXTEND_A39: HDR_L1.79 U4.V5 | length 1301.8
  Top Layer w7.87: v1(1169.29,1275.59) U4.V5@1188.98,1295.28
  MidLayer2 w5: v2(114.17,1015.75) 145.67,1015.75 448.81,1318.9 507.87,1318.9 519.68,1307.09 897.64,1307.09 948.82,1255.91 956.69,1255.91 968.5,1255.91 1149.61,1255.91 v1(1169.29,1275.59)
  Bottom Layer w7.87: v2(114.17,1015.75) HDR_L1.79@173.23,1015.74
EXTEND_A40: HDR_L1.81 U4.W5 | length 1308.3
  Top Layer w7.87: v1(1169.29,1236.22) U4.W5@1188.98,1255.91
  MidLayer2 w5: v2(114.17,984.25) 145.67,984.25 440.94,1279.53 507.87,1279.53 519.69,1291.34 807.09,1291.34 881.89,1216.54 956.69,1216.54 968.5,1216.54 1149.61,1216.54 v1(1169.29,1236.22)
  Bottom Layer w7.87: v2(114.17,984.25) HDR_L1.81@173.23,984.25
EXTEND_A41: HDR_L1.83 U4.Y5 | length 1308.3
  Top Layer w7.87: v1(1169.29,1196.85) U4.Y5@1188.98,1216.54
  MidLayer2 w5: v2(114.17,952.76) 145.67,952.75 448.81,1255.9 507.87,1255.9 519.69,1244.09 826.77,1244.09 893.7,1177.17 956.69,1177.17 968.5,1177.17 1149.61,1177.17 v1(1169.29,1196.85)
  Bottom Layer w7.87: v2(114.17,952.76) HDR_L1.83@173.23,952.75
EXTEND_A42: HDR_L1.85 U4.AB5 | length 1331.2
  Top Layer w7.87: v1(1169.29,1118.11) U4.AB5@1188.98,1137.8
  MidLayer2 w5: v2(114.17,921.26) 145.67,921.26 440.94,1216.53 507.87,1216.53 519.69,1228.34 818.9,1228.34 948.82,1098.43 952.76,1098.43 968.5,1098.42 1149.61,1098.42 v1(1169.29,1118.11)
  Bottom Layer w7.87: v2(114.17,921.26) HDR_L1.85@173.23,921.26
EXTEND_A43: HDR_L1.87 U4.AB6 | length 1403
  Top Layer w7.87: v1(1208.66,1118.11) U4.AB6@1228.35,1137.8
  MidLayer2 w5: v2(114.17,889.76) 145.67,889.76 448.81,1192.91 507.87,1192.91 526.99,1173.8 775.02,1173.8 870.08,1078.74 952.76,1078.74 968.5,1078.74 1008.86,1078.74 1028.54,1059.06 1177.17,1059.06 1188.98,1070.87 1188.98,1098.43 v1(1208.66,1118.11)
  Bottom Layer w7.87: v2(114.17,889.76) HDR_L1.87@173.23,889.76
EXTEND_A44: HDR_L1.89 U4.K6 | length 1813.6
  Top Layer w7.87: v1(1208.66,1629.92) U4.K6@1228.35,1610.24
  MidLayer3 w5: v2(114.17,858.27) 133.86,858.27 168.4,892.81 168.4,1365.25 460.63,1657.48 507.87,1657.48 523.62,1673.23 956.69,1673.23 968.5,1673.23 1055.12,1673.23 1078.74,1649.61 1188.98,1649.61 v1(1208.66,1629.92)
  Bottom Layer w7.87: v2(114.17,858.27) HDR_L1.89@173.23,858.26
EXTEND_A45: HDR_L1.91 U4.L6 | length 1810.4
  Top Layer w7.87: v1(1208.66,1590.55) U4.L6@1228.35,1570.87
  MidLayer3 w5: v2(114.17,826.77) 133.86,826.77 192.91,885.83 192.91,1358.27 468.5,1633.86 507.87,1633.86 519.68,1622.05 838.58,1622.05 850.39,1610.24 956.69,1610.24 968.5,1610.24 1188.98,1610.24 v1(1208.66,1590.55)
  Bottom Layer w7.87: v2(114.17,826.77) HDR_L1.91@173.23,826.77
EXTEND_A46: HDR_L1.93 U4.M6 | length 1816.9
  Top Layer w7.87: v1(1208.66,1551.18) U4.M6@1228.35,1531.5
  MidLayer3 w5: v2(114.17,795.28) 133.86,795.28 216.54,877.95 216.54,1350.39 460.63,1594.49 507.87,1594.49 519.68,1606.3 803.15,1606.3 838.58,1570.87 956.69,1570.87 968.5,1570.87 1039.37,1570.87 1188.98,1570.87 v1(1208.66,1551.18)
  Bottom Layer w7.87: v2(114.17,795.28) HDR_L1.93@173.23,795.27
EXTEND_A47: HDR_L1.95 U4.N6 | length 1816.9
  Top Layer w7.87: v1(1208.66,1511.81) U4.N6@1228.35,1492.13
  MidLayer3 w5: v2(114.17,763.78) 133.86,763.78 240.16,870.08 240.16,1342.52 468.5,1570.87 507.87,1570.87 519.68,1559.06 807.09,1559.06 834.65,1531.5 956.69,1531.5 968.5,1531.5 1188.98,1531.5 v1(1208.66,1511.81)
  Bottom Layer w7.87: v2(114.17,763.78) HDR_L1.95@173.23,763.78
EXTEND_A48: HDR_L1.97 U4.N8 | length 1906.8
  Top Layer w7.87: v1(1287.4,1514.76) U4.N8@1307.09,1492.13
  MidLayer3 w5: v2(114.17,732.28) 133.86,732.28 263.78,862.2 263.78,1334.65 460.63,1531.5 508.35,1531.5 508.35,1531.97 519.68,1543.31 763.78,1543.31 814.96,1492.13 956.69,1492.13 968.5,1492.13 1267.72,1492.13 v1(1287.4,1514.76)
  Bottom Layer w7.87: v2(114.17,732.28) HDR_L1.97@173.23,732.28
EXTEND_A49: HDR_L1.99 U4.P8 | length 1902
  Top Layer w7.87: v1@1287.4,1433.07 U4.P8@1307.09,1452.76
  MidLayer3 w5: v2(114.17,700.79) 133.86,700.79 287.4,854.33 287.4,1322.83 472.44,1507.87 507.87,1507.87 519.68,1496.06 700.79,1496.06 744.09,1452.76 956.69,1452.76 968.5,1452.76 1267.72,1452.76 v1(1287.4,1430.12)
  Bottom Layer w7.87: v2(114.17,700.79) HDR_L1.99@173.23,700.78
EXTEND_B0: HDR_L1.2 U4.B4 | length 914.6
  Top Layer w5: v2(500,2244.1) 759.84,2244.09 850.39,2153.54 1047.24,2153.54 1094.49,2106.3 1094.49,2039.37 1094.49,2027.56 1094.49,2019.68 1129.92,1984.25 1129.92,1944.88 U4.B4@1149.61,1925.2
  Bottom Layer w7.87: HDR_L1.2@440.94,2244.09 v2(500,2244.1)
EXTEND_B1: HDR_L1.4 U4.C4 | length 941.4
  Top Layer w7.87: v1(1129.92,1905.51) U4.C4@1149.61,1885.83
  MidLayer1 w5: v2(523.62,2212.6) 596.82,2212.6 655.72,2153.7 1047.9,2153.7 1090.55,2111.05 1090.55,2039.37 1090.55,2027.56 1090.55,1944.88 v1(1129.92,1905.51)
  Bottom Layer w7.87: HDR_L1.4@440.94,2212.6 v2(523.62,2212.6)
EXTEND_B2: HDR_L1.6 U4.E4 | length 863.6
  Top Layer w7.87: v1(1129.92,1826.77) U4.E4@1149.61,1807.09
  MidLayer1 w5: v2(500,2181.1) 614.17,2181.1 897.64,1897.64 956.69,1897.64 968.5,1897.64 980.31,1897.64 1031.5,1846.46 1074.8,1846.46 1110.24,1846.46 v1(1129.92,1826.77)
  Bottom Layer w7.87: HDR_L1.6@440.94,2181.1 v2(500,2181.1)
EXTEND_B3: HDR_L1.8 U4.E3 | length 811.2
  Top Layer w7.87: v1(1090.55,1826.77) U4.E3@1110.24,1807.09
  MidLayer1 w5: v2(523.62,2149.61) 618.11,2149.61 881.89,1885.83 956.69,1885.83 968.5,1885.83 972.44,1885.83 1031.5,1826.77 v1(1090.55,1826.77)
  Bottom Layer w7.87: HDR_L1.8@440.94,2149.6 v2(523.62,2149.61)
EXTEND_B4: HDR_L1.10 U4.F4 | length 853.8
  Top Layer w7.87: v1(1129.92,1787.4) U4.F4@1149.61,1767.72
  MidLayer1 w5: v2(500,2118.11) 622.05,2118.11 933.07,1807.09 956.69,1807.09 968.5,1807.09 1110.24,1807.09 v1(1129.92,1787.4)
  Bottom Layer w7.87: HDR_L1.10@440.94,2118.11 v2(500,2118.11)
EXTEND_B5: HDR_L1.12 U4.F3 | length 811.2
  Top Layer w7.87: v1(1090.55,1787.4) U4.F3@1110.24,1767.72
  MidLayer1 w5: v2(523.62,2086.62) 834.65,1775.59 925.2,1775.59 937.01,1787.4 956.69,1787.4 968.5,1787.4 v1(1090.55,1787.4)
  Bottom Layer w7.87: HDR_L1.12@440.94,2086.61 v2(523.62,2086.62)
EXTEND_B6: HDR_L1.14 U4.G4 | length 853.8
  Top Layer w7.87: v1(1129.92,1748.03) U4.G4@1149.61,1728.35
  MidLayer1 w5: v2(500,2055.12) 523.62,2055.12 822.84,1755.91 929.13,1755.91 940.94,1767.72 956.69,1767.72 968.5,1767.72 1110.24,1767.72 v1(1129.92,1748.03)
  Bottom Layer w7.87: HDR_L1.14@440.94,2055.12 v2(500,2055.12)
EXTEND_B7: HDR_L1.16 U4.H4 | length 961.4
  Top Layer w7.87: v1(1129.92,1708.66) U4.H4@1149.61,1688.98
  MidLayer1 w5: v2(523.62,2023.62) 818.9,1728.35 956.69,1728.35 968.5,1728.35 1110.24,1728.35 ; 996.06,1728.35 1110.24,1728.35 ; v1(1129.92,1708.66) 1110.24,1728.35
  Bottom Layer w7.87: HDR_L1.16@440.94,2023.62 v2(523.62,2023.62)
EXTEND_B8: HDR_L1.18 U4.H3 | length 794.9
  Top Layer w7.87: v1(1090.55,1708.66) U4.H3@1110.24,1688.98
  MidLayer1 w5: v2(500,1992.13) 523.62,1992.13 807.09,1708.66 956.69,1708.66 968.5,1708.66 v1(1090.55,1708.66)
  Bottom Layer w7.87: HDR_L1.18@440.94,1992.12 v2(500,1992.13)
EXTEND_B9: HDR_L1.20 U4.J4 | length 837.5
  Top Layer w7.87: v1(1129.92,1669.29) U4.J4@1149.61,1649.61
  MidLayer1 w5: v2(523.62,1960.63) 795.28,1688.98 956.69,1688.98 968.5,1688.98 1110.24,1688.98 v1(1129.92,1669.29)
  Bottom Layer w7.87: HDR_L1.20@440.94,1960.63 v2(523.62,1960.63)
EXTEND_B10: HDR_L1.22 U4.J3 | length 785.1
  Top Layer w7.87: v1(1090.55,1669.29) U4.J3@1110.24,1649.61
  MidLayer1 w5: v2(500,1929.14) 523.62,1929.14 783.47,1669.29 956.69,1669.29 968.5,1669.29 v1(1090.55,1669.29)
  Bottom Layer w7.87: HDR_L1.22@440.94,1929.13 v2(500,1929.14)
EXTEND_B11: HDR_L1.24 U4.K3 | length 788.3
  Top Layer w7.87: v1(1090.55,1629.92) U4.K3@1110.24,1610.24
  MidLayer1 w5: v2(523.62,1897.64) 763.78,1657.48 921.26,1657.48 937.01,1641.73 956.69,1641.73 968.5,1641.73 984.25,1641.73 996.06,1629.92 v1(1090.55,1629.92)
  Bottom Layer w7.87: HDR_L1.24@440.94,1897.64 v2(523.62,1897.64)
EXTEND_B12: HDR_L1.26 U4.K4 | length 831
  Top Layer w7.87: v1(1129.92,1629.92) U4.K4@1149.61,1610.24
  MidLayer1 w5: v2(500,1866.14) 523.62,1866.14 779.53,1610.24 956.69,1610.24 968.5,1610.24 996.06,1610.24 1110.24,1610.24 v1(1129.92,1629.92)
  Bottom Layer w7.87: HDR_L1.26@440.94,1866.14 v2(500,1866.14)
EXTEND_B13: HDR_L1.28 U4.L4 | length 834.2
  Top Layer w7.87: v1(1129.92,1590.55) U4.L4@1149.61,1570.87
  MidLayer1 w5: v2(523.62,1834.65) 787.4,1570.87 956.69,1570.87 968.5,1570.87 1110.24,1570.87 v1(1129.92,1590.55)
  Bottom Layer w7.87: HDR_L1.28@440.94,1834.64 v2(523.62,1834.65)
EXTEND_B14: HDR_L1.30 U4.M3 | length 781.8
  Top Layer w7.87: v1(1090.55,1551.18) U4.M3@1110.24,1531.5
  MidLayer1 w5: v2(500,1803.15) 519.68,1803.15 771.65,1551.18 956.69,1551.18 968.5,1551.18 v1(1090.55,1551.18)
  Bottom Layer w7.87: HDR_L1.30@440.94,1803.15 v2(500,1803.15)
EXTEND_B15: HDR_L1.32 U4.L8 | length 1049.1
  Top Layer w7.87: v1(1287.4,1590.55) U4.L8@1307.09,1570.87
  MidLayer1 w5: v2(523.62,1771.66) 763.78,1531.5 956.69,1531.5 968.5,1531.5 1003.94,1531.5 1137.8,1531.5 1149.61,1543.31 1149.61,1602.36 1157.48,1610.24 1267.72,1610.24 v1(1287.4,1590.55)
  Bottom Layer w7.87: HDR_L1.32@440.94,1771.65 v2(523.62,1771.66)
